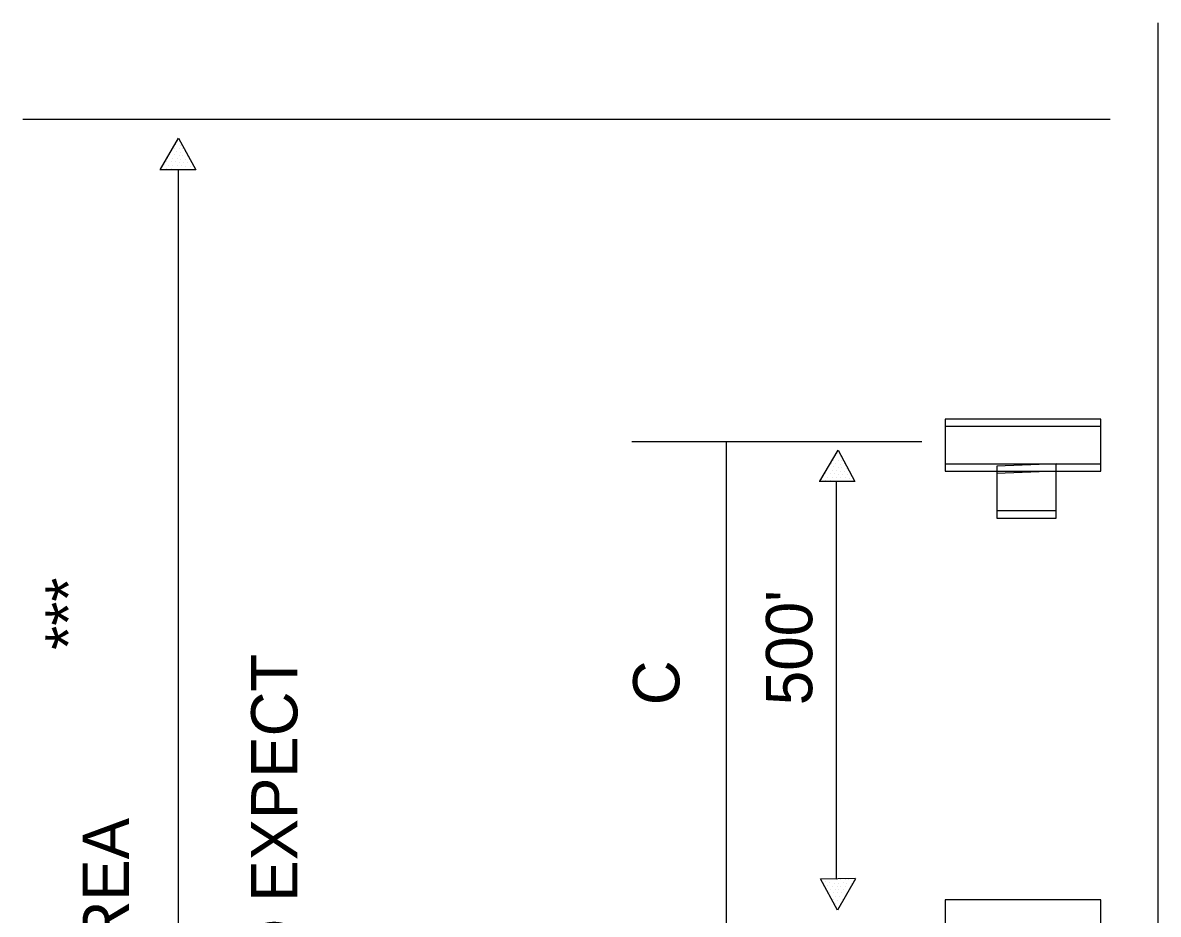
# Model space of a CAD drawing. Extents: x 610.92 to 617.75, y 610.91 to 620.34.
# Drawn here: x 614.338 to 615.809, y 619.182 to 620.337 of the extents above; entities that cross this region are included whole.
import ezdxf

# ---------------------------------------------------------------- set-up
doc = ezdxf.new("R2010")
doc.units = 0
for name, color, linetype in [('DETL-DIMS', 7, 'Continuous'), ('DETL-LINE', 7, 'Continuous'), ('DETL-NOTE', 7, 'Continuous'), ('USER-BORD', 7, 'Continuous')]:
    doc.layers.add(name, color=color, linetype=linetype)

# ---------------------------------------------------------------- blocks, each defined once
blk = doc.blocks.new('SIGN15')
at = {"layer": 'USER-BORD'}
for points in [[(-0.0013, 0.0018), (0.0011, 0.0019), (0.0011, 0.0037), (-0.0013, 0.0037)], [(-0.0031, 0.0018), (-0.0031, 0), (0.0032, 0), (0.0032, 0.0018)]]:
    blk.add_lwpolyline(points, close=True, dxfattribs=at)

msp = doc.modelspace()

# ---------------------------------------------------------------- linework, layer by layer
at = {"layer": 'DETL-DIMS'}
for p, q in [((614.3382, 620.2124), (615.7462, 620.2124)), ((614.3382, 620.2124), (615.7462, 620.2124)), ((614.5166, 620.1476), (614.5398, 620.1876)), ((614.5398, 620.1876), (614.5622, 620.1468)), ((614.531, 620.1708), (614.531, 620.1708)), ((614.5342, 620.1748), (614.5342, 620.1748)), ((614.5366, 620.1796), (614.5366, 620.1796)), ((614.539, 620.1836), (614.539, 620.1836)), ((614.5406, 620.1748), (614.5406, 620.1748)), ((614.543, 620.1788), (614.543, 620.1788)), ((614.5454, 620.174), (614.5454, 620.174)), ((614.5238, 620.1572), (614.5238, 620.1572)), ((614.5262, 620.162), (614.5262, 620.162)), ((614.5286, 620.1668), (614.5286, 620.1668)), ((614.5302, 620.1572), (614.5302, 620.1572)), ((614.5326, 620.1612), (614.5326, 620.1612)), ((614.535, 620.166), (614.535, 620.166)), ((614.5358, 620.1572), (614.5358, 620.1572)), ((614.5374, 620.17), (614.5374, 620.17)), ((614.5382, 620.1612), (614.5382, 620.1612)), ((614.5406, 620.1652), (614.5406, 620.1652)), ((614.5406, 620.1564), (614.5406, 620.1564)), ((614.543, 620.1692), (614.543, 620.1692)), ((614.543, 620.1604), (614.543, 620.1604)), ((614.5454, 620.1652), (614.5454, 620.1652)), ((614.5462, 620.1564), (614.5462, 620.1564)), ((614.5486, 620.17), (614.5486, 620.17)), ((614.5486, 620.1604), (614.5486, 620.1604)), ((614.551, 620.1644), (614.551, 620.1644)), ((614.555, 620.1596), (614.555, 620.1596)), ((614.5158, 620.1468), (614.5158, 620.1468)), ((614.5622, 620.1468), (614.5158, 620.1468)), ((614.519, 620.1492), (614.519, 620.1492)), ((614.5214, 620.1532), (614.5214, 620.1532)), ((614.5246, 620.1484), (614.5246, 620.1484)), ((614.527, 620.1524), (614.527, 620.1524)), ((614.5302, 620.1484), (614.5302, 620.1484)), ((614.5326, 620.1524), (614.5326, 620.1524)), ((614.5358, 620.1476), (614.5358, 620.1476)), ((614.5382, 620.1524), (614.5382, 620.1524)), ((614.5398, 618.1476), (614.5398, 620.1468)), ((614.5414, 620.1476), (614.5414, 620.1476)), ((614.5438, 620.1524), (614.5438, 620.1524)), ((614.547, 620.1468), (614.547, 620.1468)), ((614.5494, 620.1516), (614.5494, 620.1516)), ((614.5518, 620.1556), (614.5518, 620.1556)), ((614.555, 620.1508), (614.555, 620.1508)), ((615.127, 619.7948), (615.5022, 619.7948)), ((615.2494, 618.082), (615.2494, 619.7948)), ((615.3702, 619.7436), (615.3942, 619.7836)), ((615.3702, 619.7436), (615.3942, 619.7836)), ((615.3902, 619.7756), (615.3902, 619.7756)), ((615.3902, 619.7756), (615.3902, 619.7756)), ((615.3926, 619.7796), (615.3926, 619.7796)), ((615.3926, 619.7796), (615.3926, 619.7796)), ((615.3942, 619.7836), (615.4158, 619.7428)), ((615.3942, 619.7836), (615.4158, 619.7428)), ((615.3966, 619.7748), (615.3966, 619.7748)), ((615.3966, 619.7748), (615.3966, 619.7748)), ((615.3822, 619.7628), (615.3822, 619.7628)), ((615.3822, 619.7628), (615.3822, 619.7628)), ((615.3854, 619.7668), (615.3854, 619.7668)), ((615.3854, 619.7668), (615.3854, 619.7668)), ((615.3878, 619.7708), (615.3878, 619.7708)), ((615.3878, 619.7708), (615.3878, 619.7708)), ((615.3886, 619.762), (615.3886, 619.762)), ((615.3886, 619.762), (615.3886, 619.762)), ((615.391, 619.766), (615.391, 619.766)), ((615.391, 619.766), (615.391, 619.766)), ((615.3942, 619.7708), (615.3942, 619.7708)), ((615.3942, 619.7708), (615.3942, 619.7708)), ((615.3942, 619.7612), (615.3942, 619.7612)), ((615.3942, 619.7612), (615.3942, 619.7612)), ((615.3966, 619.7652), (615.3966, 619.7652)), ((615.3966, 619.7652), (615.3966, 619.7652)), ((615.399, 619.77), (615.399, 619.77)), ((615.399, 619.77), (615.399, 619.77)), ((615.399, 619.7612), (615.399, 619.7612)), ((615.399, 619.7612), (615.399, 619.7612)), ((615.4022, 619.766), (615.4022, 619.766)), ((615.4022, 619.766), (615.4022, 619.766)), ((615.4046, 619.7604), (615.4046, 619.7604)), ((615.4046, 619.7604), (615.4046, 619.7604)), ((615.3726, 619.7452), (615.3726, 619.7452)), ((615.3726, 619.7452), (615.3726, 619.7452)), ((615.375, 619.7492), (615.375, 619.7492)), ((615.375, 619.7492), (615.375, 619.7492)), ((615.3774, 619.7532), (615.3774, 619.7532)), ((615.3774, 619.7532), (615.3774, 619.7532)), ((615.3782, 619.7444), (615.3782, 619.7444)), ((615.3782, 619.7444), (615.3782, 619.7444)), ((615.3798, 619.758), (615.3798, 619.758)), ((615.3798, 619.758), (615.3798, 619.758)), ((615.3806, 619.7484), (615.3806, 619.7484)), ((615.3806, 619.7484), (615.3806, 619.7484)), ((615.3838, 619.7532), (615.3838, 619.7532)), ((615.3838, 619.7532), (615.3838, 619.7532)), ((615.3838, 619.7444), (615.3838, 619.7444)), ((615.3838, 619.7444), (615.3838, 619.7444)), ((615.3862, 619.7572), (615.3862, 619.7572)), ((615.3862, 619.7572), (615.3862, 619.7572)), ((615.3862, 619.7484), (615.3862, 619.7484)), ((615.3862, 619.7484), (615.3862, 619.7484)), ((615.3894, 619.7532), (615.3894, 619.7532)), ((615.3894, 619.7532), (615.3894, 619.7532)), ((615.3918, 619.7572), (615.3918, 619.7572)), ((615.3918, 619.7572), (615.3918, 619.7572)), ((615.3918, 619.7484), (615.3918, 619.7484)), ((615.3918, 619.7484), (615.3918, 619.7484)), ((615.3942, 619.7524), (615.3942, 619.7524)), ((615.3942, 619.7524), (615.3942, 619.7524)), ((615.3966, 619.7564), (615.3966, 619.7564)), ((615.3966, 619.7564), (615.3966, 619.7564)), ((615.3974, 619.7484), (615.3974, 619.7484)), ((615.3974, 619.7484), (615.3974, 619.7484)), ((615.3998, 619.7524), (615.3998, 619.7524)), ((615.3998, 619.7524), (615.3998, 619.7524)), ((615.4022, 619.7564), (615.4022, 619.7564)), ((615.4022, 619.7564), (615.4022, 619.7564)), ((615.403, 619.7476), (615.403, 619.7476)), ((615.403, 619.7476), (615.403, 619.7476)), ((615.4062, 619.7516), (615.4062, 619.7516)), ((615.4062, 619.7516), (615.4062, 619.7516)), ((615.4086, 619.7556), (615.4086, 619.7556)), ((615.4086, 619.7556), (615.4086, 619.7556)), ((615.4086, 619.7468), (615.4086, 619.7468)), ((615.4086, 619.7468), (615.4086, 619.7468)), ((615.3694, 619.7428), (615.3694, 619.7428)), ((615.4158, 619.7428), (615.3694, 619.7428)), ((615.4158, 619.7428), (615.3694, 619.7428)), ((615.3694, 619.7428), (615.3694, 619.7428)), ((615.3894, 619.7436), (615.3894, 619.7436)), ((615.3894, 619.7436), (615.3894, 619.7436)), ((615.3918, 619.2284), (615.3918, 619.7428)), ((615.395, 619.7436), (615.395, 619.7436)), ((615.395, 619.7436), (615.395, 619.7436)), ((615.4006, 619.7436), (615.4006, 619.7436)), ((615.4006, 619.7436), (615.4006, 619.7436)), ((615.3918, 619.2836), (615.3918, 619.7076)), ((615.371, 619.2284), (615.4166, 619.2292)), ((615.371, 619.2284), (615.4166, 619.2292)), ((615.3934, 619.1876), (615.371, 619.2284)), ((615.3934, 619.1876), (615.371, 619.2284)), ((615.3782, 619.2244), (615.3782, 619.2244)), ((615.3782, 619.2244), (615.3782, 619.2244)), ((615.3782, 619.2156), (615.3782, 619.2156)), ((615.3782, 619.2156), (615.3782, 619.2156)), ((615.3806, 619.2196), (615.3806, 619.2196)), ((615.3806, 619.2196), (615.3806, 619.2196)), ((615.383, 619.2236), (615.383, 619.2236)), ((615.383, 619.2236), (615.383, 619.2236)), ((615.3854, 619.2284), (615.3854, 619.2284)), ((615.3854, 619.2284), (615.3854, 619.2284)), ((615.387, 619.2188), (615.387, 619.2188)), ((615.387, 619.2188), (615.387, 619.2188)), ((615.3894, 619.2228), (615.3894, 619.2228)), ((615.3894, 619.2228), (615.3894, 619.2228)), ((615.3918, 619.2276), (615.3918, 619.2276)), ((615.3918, 619.2276), (615.3918, 619.2276)), ((615.3926, 619.2188), (615.3926, 619.2188)), ((615.3926, 619.2188), (615.3926, 619.2188)), ((615.4166, 619.2284), (615.3934, 619.1876)), ((615.4166, 619.2284), (615.3934, 619.1876)), ((615.395, 619.2228), (615.395, 619.2228)), ((615.395, 619.2228), (615.395, 619.2228)), ((615.3974, 619.2276), (615.3974, 619.2276)), ((615.3974, 619.2276), (615.3974, 619.2276)), ((615.3974, 619.2188), (615.3974, 619.2188)), ((615.3974, 619.2188), (615.3974, 619.2188)), ((615.4006, 619.2236), (615.4006, 619.2236)), ((615.4006, 619.2236), (615.4006, 619.2236)), ((615.403, 619.2276), (615.403, 619.2276)), ((615.403, 619.2276), (615.403, 619.2276)), ((615.403, 619.218), (615.403, 619.218)), ((615.403, 619.218), (615.403, 619.218)), ((615.4054, 619.2228), (615.4054, 619.2228)), ((615.4054, 619.2228), (615.4054, 619.2228)), ((615.4078, 619.2276), (615.4078, 619.2276)), ((615.4078, 619.2276), (615.4078, 619.2276)), ((615.4094, 619.218), (615.4094, 619.218)), ((615.4094, 619.218), (615.4094, 619.218)), ((615.4118, 619.2228), (615.4118, 619.2228)), ((615.4118, 619.2228), (615.4118, 619.2228)), ((615.4142, 619.2268), (615.4142, 619.2268)), ((615.4142, 619.2268), (615.4142, 619.2268)), ((615.4166, 619.2292), (615.4166, 619.2292)), ((615.4166, 619.2292), (615.4166, 619.2292)), ((615.3822, 619.2108), (615.3822, 619.2108)), ((615.3822, 619.2108), (615.3822, 619.2108)), ((615.3846, 619.2148), (615.3846, 619.2148)), ((615.3846, 619.2148), (615.3846, 619.2148)), ((615.3846, 619.2052), (615.3846, 619.2052)), ((615.3846, 619.2052), (615.3846, 619.2052)), ((615.3878, 619.21), (615.3878, 619.21)), ((615.3878, 619.21), (615.3878, 619.21)), ((615.3878, 619.2012), (615.3878, 619.2012)), ((615.3878, 619.2012), (615.3878, 619.2012)), ((615.3902, 619.2148), (615.3902, 619.2148)), ((615.3902, 619.2148), (615.3902, 619.2148)), ((615.3902, 619.206), (615.3902, 619.206)), ((615.3902, 619.206), (615.3902, 619.206)), ((615.3926, 619.21), (615.3926, 619.21)), ((615.3926, 619.21), (615.3926, 619.21)), ((615.3934, 619.2004), (615.3934, 619.2004)), ((615.3934, 619.2004), (615.3934, 619.2004)), ((615.395, 619.214), (615.395, 619.214)), ((615.395, 619.214), (615.395, 619.214)), ((615.3958, 619.206), (615.3958, 619.206)), ((615.3958, 619.206), (615.3958, 619.206)), ((615.3982, 619.21), (615.3982, 619.21)), ((615.3982, 619.21), (615.3982, 619.21)), ((615.3998, 619.2012), (615.3998, 619.2012)), ((615.3998, 619.2012), (615.3998, 619.2012)), ((615.4006, 619.214), (615.4006, 619.214)), ((615.4006, 619.214), (615.4006, 619.214)), ((615.4022, 619.2052), (615.4022, 619.2052)), ((615.4022, 619.2052), (615.4022, 619.2052)), ((615.4046, 619.2092), (615.4046, 619.2092)), ((615.4046, 619.2092), (615.4046, 619.2092)), ((615.407, 619.2132), (615.407, 619.2132)), ((615.407, 619.2132), (615.407, 619.2132)), ((615.391, 619.1964), (615.391, 619.1964)), ((615.391, 619.1964), (615.391, 619.1964)), ((615.3942, 619.1916), (615.3942, 619.1916)), ((615.3942, 619.1916), (615.3942, 619.1916)), ((615.3966, 619.1956), (615.3966, 619.1956)), ((615.3966, 619.1956), (615.3966, 619.1956))]:
    msp.add_line(p, q, dxfattribs=at)
at = {"layer": 'DETL-LINE'}
msp.add_line((615.8086, 613.3204), (615.8086, 620.3372), dxfattribs=at)

# ---------------------------------------------------------------- block references
at = {"layer": 'DETL-LINE', "xscale": 32, "yscale": 32, "rotation": 180}
for p in [(615.6349, 619.8236), (615.6349, 619.814), (615.6349, 619.2012)]:
    msp.add_blockref('SIGN15', p, dxfattribs=at)

# ---------------------------------------------------------------- texts
at = {"layer": 'DETL-NOTE'}
for s, p in [('***', (614.4274, 619.5248)), ("500'", (615.3605, 619.4532)), ('--TELLS TRAFFIC WHAT TO EXPECT', (614.6939, 618.1246)), ('C', (615.1885, 619.4532)), ('ADVANCE WARNING AREA', (614.4757, 618.2684))]:
    msp.add_text(s, height=0.06, rotation=90, dxfattribs=at).set_placement(p)

doc.saveas('drawing.dxf')
